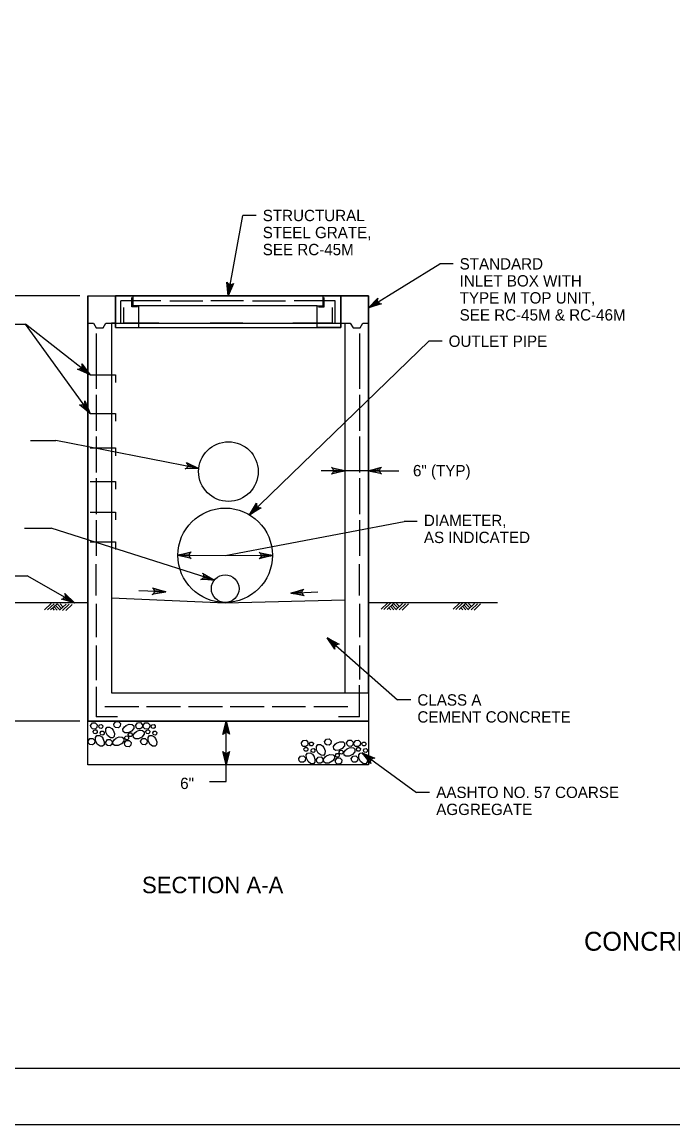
# Model space of a CAD drawing. Extents: x 636462 to 639890, y 299944 to 300538.
# Drawn here: x 639148.1 to 639320.2, y 299944.4 to 300236.1 of the extents above; entities that cross this region are included whole.
import ezdxf

# ---------------------------------------------------------------- set-up
doc = ezdxf.new("R2010")
doc.units = 0
for name, color, linetype in [('1', 7, 'Continuous'), ('Default', 7, 'Continuous'), ('PLT-BNDY', 7, 'Continuous')]:
    doc.layers.add(name, color=color, linetype=linetype)

msp = doc.modelspace()

# ---------------------------------------------------------------- linework, layer by layer
at = {"layer": '1'}
msp.add_lwpolyline([(639810.91, 299959.45), (639810.91, 300523.45), (639024.91, 300523.45), (639024.91, 299959.45), (639810.91, 299959.45), (639810.91, 299985.81), (639610.91, 299985.81), (639610.91, 300050.49), (639810.91, 300050.49), (639810.91, 300079.45), (639610.91, 300079.45), (639610.91, 299959.45), (639689.72, 299959.45), (639689.72, 299985.81), (639689.72, 299959.45), (639766.72, 299959.45), (639766.72, 299985.81), (639766.72, 299973.49), (639810.91, 299973.49)], dxfattribs=at)
at = {"layer": 'Default'}
for p, q in [((639202.59, 300163.65), (639206.52, 300184.9)), ((639210.01, 300184.9), (639206.52, 300184.9)), ((639239.68, 300160.5), (639258.57, 300172.12)), ((639262.07, 300172.12), (639258.57, 300172.12)), ((639163.38, 300163.65), (639084.63, 300163.65)), ((639165.5, 300163.65), (639165.5, 300051.22)), ((639165.5, 300163.65), (639239.68, 300163.65)), ((639172.8, 300155.32), (639172.8, 300163.65)), ((639232.38, 300163.65), (639172.8, 300163.65)), ((639177.17, 300160.73), (639177.17, 300163.25)), ((639177.48, 300161.04), (639177.48, 300163.65)), ((639227.7, 300161.04), (639227.7, 300163.65)), ((639228.01, 300160.73), (639228.01, 300163.25)), ((639232.38, 300155.32), (639232.38, 300163.65)), ((639239.68, 300163.65), (639239.68, 300051.22)), ((639174.23, 300156.34), (639174.23, 300162.34)), ((639184.84, 300162.34), (639174.23, 300162.34)), ((639174.99, 300156.4), (639174.99, 300160.6)), ((639178.68, 300160.73), (639177.17, 300160.73)), ((639177.48, 300161.04), (639179.04, 300161.04)), ((639179.04, 300155.32), (639179.04, 300161.04)), ((639226.14, 300161.04), (639179.04, 300161.04)), ((639187.23, 300162.34), (639195.92, 300162.34)), ((639206.7, 300162.34), (639198.01, 300162.34)), ((639209.09, 300162.34), (639217.79, 300162.34)), ((639230.95, 300162.34), (639220.06, 300162.34)), ((639226.14, 300155.32), (639226.14, 300161.04)), ((639226.14, 300161.04), (639227.7, 300161.04)), ((639226.5, 300160.73), (639228.01, 300160.73)), ((639230.19, 300156.4), (639230.19, 300160.6)), ((639230.95, 300156.34), (639230.95, 300162.34)), ((639145.5, 300156.21), (639149, 300156.21)), ((639166.1, 300142.79), (639149, 300156.21)), ((639166.1, 300132.55), (639149, 300156.21)), ((639165.5, 300156.4), (639166.99, 300156.4)), ((639166.99, 300156.4), (639167.7, 300155.17)), ((639167.7, 300155.17), (639169.55, 300155.17)), ((639169.55, 300155.17), (639170.27, 300156.4)), ((639170.27, 300156.4), (639171.75, 300156.4)), ((639171.75, 300156.4), (639233.43, 300156.4)), ((639171.75, 300156.4), (639171.75, 300058.74)), ((639172.8, 300155.32), (639232.38, 300155.32)), ((639184.29, 300156.4), (639174.99, 300156.4)), ((639186.68, 300156.4), (639195.77, 300156.4)), ((639206.52, 300156.4), (639197.88, 300156.4)), ((639209.09, 300156.4), (639217.73, 300156.4)), ((639230.19, 300156.4), (639219.75, 300156.4)), ((639233.43, 300156.4), (639234.91, 300156.4)), ((639233.43, 300156.4), (639233.43, 300058.74)), ((639234.91, 300156.4), (639235.63, 300155.17)), ((639235.63, 300155.17), (639237.48, 300155.17)), ((639237.48, 300155.17), (639238.19, 300156.4)), ((639238.19, 300156.4), (639239.68, 300156.4)), ((639167.72, 300153.71), (639167.72, 300139.04)), ((639208.24, 300105.78), (639255.66, 300151.67)), ((639237.36, 300153.71), (639237.36, 300139.04)), ((639259.16, 300151.67), (639255.66, 300151.67)), ((639167.72, 300137.5), (639167.72, 300128)), ((639237.36, 300137.5), (639237.36, 300128)), ((639150.33, 300125.41), (639157.02, 300125.41)), ((639194.86, 300118.04), (639157.02, 300125.41)), ((639167.72, 300126.46), (639167.72, 300116.96)), ((639237.36, 300126.46), (639237.36, 300116.96)), ((639239.68, 300117.44), (639227.18, 300117.44)), ((639239.68, 300117.44), (639247.72, 300117.44)), ((639167.72, 300115.42), (639167.72, 300105.92)), ((639237.36, 300115.42), (639237.36, 300105.92)), ((639148.75, 300102.28), (639155.8, 300102.28)), ((639198.98, 300088.51), (639155.8, 300102.28)), ((639167.72, 300104.38), (639167.72, 300094.88)), ((639201.83, 300095.03), (639249.12, 300103.97)), ((639237.36, 300104.38), (639237.36, 300094.88)), ((639252.62, 300103.97), (639249.12, 300103.97)), ((639189.34, 300095.06), (639214.33, 300094.99)), ((639167.72, 300084.46), (639167.72, 300092.72)), ((639237.36, 300084.46), (639237.36, 300092.72)), ((639126.35, 300089.67), (639149.47, 300089.67)), ((639161.98, 300082.47), (639149.47, 300089.67)), ((639186.1, 300085.38), (639178.97, 300085.7)), ((639219.21, 300085.06), (639226.34, 300085.39)), ((639165.5, 300082.47), (639131.4, 300082.47)), ((639154.08, 300080.67), (639155.81, 300082.28)), ((639154.86, 300080.64), (639156.6, 300082.26)), ((639155.67, 300080.61), (639157.41, 300082.23)), ((639156.58, 300081.46), (639157.44, 300080.55)), ((639156.96, 300081.81), (639158.08, 300080.61)), ((639157.38, 300082.24), (639158.52, 300081.01)), ((639158, 300080.53), (639159.75, 300082.16)), ((639158.19, 300082.21), (639158.93, 300081.41)), ((639158.85, 300080.5), (639160.58, 300082.1)), ((639159.66, 300080.47), (639161.38, 300082.08)), ((639167.72, 300082.25), (639167.72, 300073.44)), ((639171.75, 300083.84), (639201.83, 300082.47)), ((639201.83, 300082.47), (639233.43, 300083.31)), ((639237.36, 300082.25), (639237.36, 300073.44)), ((639239.68, 300082.57), (639273.79, 300082.57)), ((639243.03, 300080.79), (639244.76, 300082.41)), ((639243.81, 300080.77), (639245.55, 300082.39)), ((639244.62, 300080.74), (639246.36, 300082.36)), ((639245.11, 300081.2), (639245.6, 300080.68)), ((639245.53, 300081.59), (639246.38, 300080.68)), ((639245.9, 300081.94), (639247.02, 300080.74)), ((639246.32, 300082.36), (639247.47, 300081.14)), ((639246.95, 300080.66), (639248.7, 300082.29)), ((639247.13, 300082.33), (639247.88, 300081.53)), ((639247.8, 300080.63), (639249.52, 300082.23)), ((639248.61, 300080.6), (639250.33, 300082.2)), ((639262.07, 300080.79), (639263.8, 300082.41)), ((639262.85, 300080.77), (639264.59, 300082.39)), ((639263.66, 300080.74), (639265.4, 300082.36)), ((639264.15, 300081.2), (639264.64, 300080.68)), ((639264.57, 300081.59), (639265.42, 300080.68)), ((639264.94, 300081.94), (639266.06, 300080.74)), ((639265.36, 300082.36), (639266.51, 300081.14)), ((639265.99, 300080.66), (639267.74, 300082.29)), ((639266.17, 300082.33), (639266.92, 300081.53)), ((639266.84, 300080.63), (639268.56, 300082.23)), ((639267.65, 300080.6), (639269.37, 300082.2)), ((639156.17, 300081.07), (639156.65, 300080.55)), ((639228.79, 300073.25), (639247.41, 300056.82)), ((639167.72, 300071.18), (639167.72, 300062.09)), ((639237.36, 300071.18), (639237.36, 300062.19)), ((639167.72, 300060.25), (639167.72, 300052.38)), ((639171.75, 300058.74), (639233.43, 300058.74)), ((639237.36, 300052.38), (639237.36, 300060.76)), ((639169.98, 300055.12), (639178.97, 300055.12)), ((639181.04, 300055.12), (639190.04, 300055.12)), ((639192.11, 300055.12), (639201.1, 300055.12)), ((639203.17, 300055.12), (639212.17, 300055.12)), ((639214.24, 300055.12), (639223.05, 300055.12)), ((639225.3, 300055.12), (639234.29, 300055.12)), ((639250.9, 300056.82), (639247.41, 300056.82)), ((639173.33, 300052.38), (639167.72, 300052.38)), ((639237.36, 300052.38), (639231.75, 300052.38)), ((639163.38, 300051.22), (639084.63, 300051.22)), ((639239.68, 300051.22), (639165.5, 300051.22)), ((639238.03, 300042.81), (639252.38, 300032.39)), ((639255.88, 300032.39), (639252.38, 300032.39))]:
    msp.add_line(p, q, dxfattribs=at)
for points in [[(639203.76, 300166.72), (639204.03, 300166.95), (639202.59, 300163.65), (639203.76, 300166.72), (639203.36, 300166.59), (639202.59, 300163.65), (639202.84, 300166.68), (639202.51, 300166.92), (639202.59, 300163.65), (639202.3, 300167.24), (639202.51, 300166.92)], [(639242.77, 300161.62), (639243.12, 300161.57), (639239.68, 300160.5), (639242.77, 300161.62), (639242.41, 300161.84), (639239.68, 300160.5), (639242.14, 300162.29), (639242.1, 300162.7), (639239.68, 300160.5), (639242.21, 300163.06), (639242.1, 300162.7)], [(639163.98, 300145.31), (639163.91, 300145.65), (639166.1, 300142.79), (639163.98, 300145.31), (639163.9, 300144.89), (639166.1, 300142.79), (639163.58, 300144.48), (639163.2, 300144.3), (639166.1, 300142.79), (639162.82, 300144.28), (639163.2, 300144.3)], [(639166.1, 300142.79), (639172.8, 300142.79), (639172.8, 300140.74)], [(639164.71, 300135.54), (639164.73, 300135.89), (639166.1, 300132.55), (639164.71, 300135.54), (639164.52, 300135.16), (639166.1, 300132.55), (639164.1, 300134.84), (639163.69, 300134.77), (639166.1, 300132.55), (639163.32, 300134.85), (639163.69, 300134.77)], [(639166.1, 300132.55), (639172.8, 300132.55), (639172.8, 300130.51)], [(639166.1, 300123.44), (639172.8, 300123.44), (639172.8, 300121.4)], [(639191.82, 300119.33), (639191.6, 300119.6), (639194.86, 300118.04), (639191.82, 300119.33), (639191.94, 300118.92), (639194.86, 300118.04), (639191.84, 300118.41), (639191.58, 300118.08), (639194.86, 300118.04), (639191.26, 300117.89), (639191.58, 300118.08)], [(639230.19, 300118.06), (639229.93, 300118.29), (639233.43, 300117.44), (639230.19, 300118.06), (639230.39, 300117.69), (639233.43, 300117.44), (639230.4, 300117.17), (639230.22, 300116.79), (639233.43, 300117.44), (639229.94, 300116.54), (639230.22, 300116.79)], [(639242.91, 300116.82), (639243.18, 300116.6), (639239.68, 300117.44), (639242.91, 300116.82), (639242.71, 300117.19), (639239.68, 300117.44), (639242.7, 300117.72), (639242.88, 300118.09), (639239.68, 300117.44), (639243.16, 300118.35), (639242.88, 300118.09)], [(639166.1, 300114.56), (639172.8, 300114.56), (639172.8, 300112.51)], [(639211.02, 300107.56), (639211.37, 300107.59), (639208.24, 300105.78), (639211.02, 300107.56), (639210.62, 300107.7), (639208.24, 300105.78), (639210.25, 300108.07), (639210.12, 300108.47), (639208.24, 300105.78), (639210.15, 300108.84), (639210.12, 300108.47)], [(639166.1, 300106.5), (639172.8, 300106.5), (639172.8, 300104.45)], [(639166.1, 300098.64), (639172.8, 300098.64), (639172.8, 300096.59)], [(639192.57, 300094.42), (639192.84, 300094.19), (639189.34, 300095.06), (639192.57, 300094.42), (639192.38, 300094.79), (639189.34, 300095.06), (639192.37, 300095.31), (639192.56, 300095.69), (639189.34, 300095.06), (639192.84, 300095.94), (639192.56, 300095.69)], [(639211.09, 300095.62), (639210.82, 300095.84), (639214.33, 300094.99), (639211.09, 300095.62), (639211.29, 300095.25), (639214.33, 300094.99), (639211.3, 300094.72), (639211.12, 300094.35), (639214.33, 300094.99), (639210.84, 300094.09), (639211.12, 300094.35)], [(639196.06, 300090.04), (639195.86, 300090.33), (639198.98, 300088.51), (639196.06, 300090.04), (639196.14, 300089.62), (639198.98, 300088.51), (639196, 300089.12), (639195.72, 300088.81), (639198.98, 300088.51), (639195.38, 300088.65), (639195.72, 300088.81)], [(639159.52, 300084.66), (639159.4, 300084.99), (639161.98, 300082.47), (639159.52, 300084.66), (639159.5, 300084.24), (639161.98, 300082.47), (639159.24, 300083.79), (639158.89, 300083.56), (639161.98, 300082.47), (639158.52, 300083.48), (639158.89, 300083.56)], [(639182.9, 300086.19), (639182.64, 300086.42), (639186.1, 300085.38), (639182.9, 300086.19), (639183.08, 300085.8), (639186.1, 300085.38), (639183.06, 300085.28), (639182.85, 300084.91), (639186.1, 300085.38), (639182.56, 300084.68), (639182.85, 300084.91)], [(639222.47, 300084.59), (639222.75, 300084.38), (639219.21, 300085.06), (639222.47, 300084.59), (639222.26, 300084.95), (639219.21, 300085.06), (639222.22, 300085.48), (639222.39, 300085.86), (639219.21, 300085.06), (639222.66, 300086.13), (639222.39, 300085.86)], [(639230.77, 300070.62), (639230.82, 300070.27), (639228.79, 300073.25), (639230.77, 300070.62), (639230.87, 300071.03), (639228.79, 300073.25), (639231.22, 300071.42), (639231.6, 300071.58), (639228.79, 300073.25), (639231.98, 300071.58), (639231.6, 300071.58)], [(639166.26, 300050.09), (639166.73, 300050.75), (639167.49, 300050.8), (639168.01, 300050.26), (639167.93, 300049.5), (639167.47, 300049.11), (639166.73, 300049.17), (639166.38, 300049.5), (639166.26, 300050.09)], [(639168.4, 300049.88), (639168.69, 300050.28), (639169.14, 300050.31), (639169.45, 300049.98), (639169.4, 300049.53), (639169.12, 300049.3), (639168.68, 300049.33), (639168.47, 300049.53), (639168.4, 300049.88)], [(639172.22, 300048.86), (639172.56, 300047.99), (639172.49, 300047.18), (639172.13, 300046.79), (639171.47, 300046.81), (639170.73, 300047.39), (639170.28, 300048.29), (639170.26, 300049.14), (639170.6, 300049.61), (639171.28, 300049.66), (639171.88, 300049.27), (639172.24, 300048.83)], [(639172.41, 300050.45), (639172.88, 300051.11), (639173.63, 300051.16), (639174.15, 300050.62), (639174.07, 300049.86), (639173.61, 300049.47), (639172.87, 300049.53), (639172.52, 300049.86), (639172.41, 300050.44)], [(639175.59, 300050.05), (639176.47, 300050.4), (639177.28, 300050.33), (639177.66, 300049.97), (639177.65, 300049.31), (639177.06, 300048.57), (639176.16, 300048.12), (639175.32, 300048.1), (639174.84, 300048.44), (639174.79, 300049.12), (639175.18, 300049.72), (639175.62, 300050.08)], [(639178.21, 300050.11), (639178.68, 300050.78), (639179.43, 300050.83), (639179.95, 300050.28), (639179.88, 300049.53), (639179.41, 300049.14), (639178.67, 300049.19), (639178.32, 300049.53), (639178.21, 300050.11)], [(639180.14, 300050.09), (639180.61, 300050.75), (639181.36, 300050.8), (639181.89, 300050.26), (639181.81, 300049.5), (639181.35, 300049.11), (639180.61, 300049.17), (639180.26, 300049.5), (639180.14, 300050.09)], [(639182.28, 300049.88), (639182.56, 300050.28), (639183.01, 300050.31), (639183.33, 300049.98), (639183.28, 300049.53), (639183, 300049.3), (639182.56, 300049.33), (639182.35, 300049.53), (639182.28, 300049.88)], [(639197.65, 300035.28), (639202.07, 300035.28), (639202.07, 300051.22)], [(639201.47, 300047.98), (639201.25, 300047.71), (639202.07, 300051.22), (639201.47, 300047.98), (639201.84, 300048.18), (639202.07, 300051.22), (639202.37, 300048.19), (639202.74, 300048.01), (639202.07, 300051.22), (639203, 300047.74), (639202.74, 300048.01)], [(639165.59, 300045.93), (639166.06, 300046.6), (639166.81, 300046.64), (639167.33, 300046.1), (639167.26, 300045.34), (639166.79, 300044.96), (639166.05, 300045.01), (639165.7, 300045.35), (639165.59, 300045.93)], [(639166.95, 300048.47), (639167.23, 300048.87), (639167.68, 300048.9), (639167.99, 300048.57), (639167.95, 300048.12), (639167.67, 300047.88), (639167.23, 300047.92), (639167.02, 300048.12), (639166.95, 300048.47)], [(639169.51, 300046.65), (639169.86, 300045.77), (639169.79, 300044.96), (639169.42, 300044.58), (639168.77, 300044.59), (639168.02, 300045.17), (639167.57, 300046.07), (639167.56, 300046.92), (639167.9, 300047.4), (639168.57, 300047.44), (639169.18, 300047.06), (639169.53, 300046.61)], [(639168.8, 300048.14), (639169.08, 300048.54), (639169.53, 300048.56), (639169.85, 300048.24), (639169.8, 300047.79), (639169.52, 300047.55), (639169.08, 300047.59), (639168.87, 300047.79), (639168.8, 300048.14)], [(639170.23, 300045.66), (639170.7, 300046.33), (639171.45, 300046.37), (639171.98, 300045.83), (639171.9, 300045.07), (639171.44, 300044.69), (639170.7, 300044.74), (639170.35, 300045.08), (639170.23, 300045.66)], [(639172.94, 300046.69), (639173.82, 300047.04), (639174.63, 300046.97), (639175.01, 300046.6), (639175, 300045.95), (639174.42, 300045.2), (639173.52, 300044.75), (639172.67, 300044.74), (639172.19, 300045.08), (639172.15, 300045.75), (639172.54, 300046.36), (639172.98, 300046.71)], [(639175.25, 300046.88), (639175.53, 300047.28), (639175.98, 300047.31), (639176.3, 300046.98), (639176.25, 300046.53), (639175.97, 300046.3), (639175.53, 300046.33), (639175.32, 300046.53), (639175.25, 300046.88)], [(639176.22, 300047.7), (639176.5, 300048.1), (639176.95, 300048.12), (639177.27, 300047.8), (639177.22, 300047.34), (639176.94, 300047.11), (639176.5, 300047.15), (639176.29, 300047.35), (639176.22, 300047.7)], [(639178.32, 300048.48), (639179.2, 300048.83), (639180, 300048.76), (639180.39, 300048.4), (639180.37, 300047.74), (639179.79, 300047), (639178.89, 300046.55), (639178.04, 300046.53), (639177.57, 300046.87), (639177.52, 300047.55), (639177.91, 300048.15), (639178.35, 300048.5)], [(639179.47, 300045.93), (639179.94, 300046.6), (639180.69, 300046.64), (639181.21, 300046.1), (639181.13, 300045.34), (639180.67, 300044.96), (639179.93, 300045.01), (639179.58, 300045.35), (639179.47, 300045.93)], [(639180.83, 300048.47), (639181.11, 300048.87), (639181.56, 300048.9), (639181.87, 300048.57), (639181.83, 300048.12), (639181.55, 300047.88), (639181.1, 300047.92), (639180.9, 300048.12), (639180.83, 300048.47)], [(639183.39, 300046.65), (639183.74, 300045.77), (639183.67, 300044.96), (639183.3, 300044.58), (639182.65, 300044.59), (639181.9, 300045.17), (639181.45, 300046.07), (639181.44, 300046.92), (639181.78, 300047.4), (639182.45, 300047.44), (639183.06, 300047.06), (639183.41, 300046.61)], [(639182.68, 300048.14), (639182.96, 300048.54), (639183.41, 300048.56), (639183.72, 300048.24), (639183.68, 300047.79), (639183.4, 300047.55), (639182.96, 300047.59), (639182.75, 300047.79), (639182.68, 300048.14)], [(639228.12, 300045.83), (639228.59, 300046.49), (639229.34, 300046.54), (639229.86, 300046), (639229.79, 300045.24), (639229.32, 300044.85), (639228.58, 300044.91), (639228.23, 300045.24), (639228.12, 300045.83)], [(639233.93, 300045.49), (639234.4, 300046.16), (639235.15, 300046.21), (639235.67, 300045.66), (639235.59, 300044.91), (639235.13, 300044.52), (639234.39, 300044.58), (639234.04, 300044.91), (639233.93, 300045.49)], [(639175.22, 300045.41), (639175.69, 300046.08), (639176.44, 300046.12), (639176.96, 300045.58), (639176.89, 300044.82), (639176.42, 300044.44), (639175.68, 300044.49), (639175.33, 300044.83), (639175.22, 300045.41)], [(639221.98, 300045.47), (639222.45, 300046.13), (639223.2, 300046.18), (639223.72, 300045.64), (639223.65, 300044.88), (639223.18, 300044.49), (639222.44, 300044.55), (639222.09, 300044.89), (639221.98, 300045.47)], [(639222.66, 300043.85), (639222.95, 300044.25), (639223.4, 300044.28), (639223.71, 300043.95), (639223.66, 300043.5), (639223.39, 300043.27), (639222.94, 300043.3), (639222.73, 300043.5), (639222.66, 300043.85)], [(639224.12, 300045.26), (639224.4, 300045.66), (639224.85, 300045.69), (639225.16, 300045.36), (639225.12, 300044.91), (639224.84, 300044.68), (639224.4, 300044.71), (639224.19, 300044.91), (639224.12, 300045.26)], [(639224.51, 300043.52), (639224.8, 300043.92), (639225.25, 300043.94), (639225.56, 300043.62), (639225.51, 300043.17), (639225.24, 300042.93), (639224.79, 300042.97), (639224.58, 300043.17), (639224.52, 300043.52)], [(639227.93, 300044.24), (639228.28, 300043.37), (639228.21, 300042.56), (639227.84, 300042.17), (639227.19, 300042.19), (639226.44, 300042.77), (639225.99, 300043.67), (639225.98, 300044.52), (639226.32, 300045), (639226.99, 300045.04), (639227.6, 300044.65), (639227.95, 300044.21)], [(639231.3, 300045.43), (639232.18, 300045.78), (639232.99, 300045.71), (639233.37, 300045.35), (639233.36, 300044.69), (639232.78, 300043.95), (639231.88, 300043.5), (639231.03, 300043.48), (639230.55, 300043.82), (639230.51, 300044.5), (639230.9, 300045.1), (639231.34, 300045.46)], [(639231.94, 300043.08), (639232.22, 300043.48), (639232.67, 300043.5), (639232.98, 300043.18), (639232.94, 300042.73), (639232.66, 300042.49), (639232.21, 300042.53), (639232.01, 300042.73), (639231.94, 300043.08)], [(639234.03, 300043.86), (639234.91, 300044.21), (639235.72, 300044.14), (639236.1, 300043.78), (639236.09, 300043.12), (639235.51, 300042.38), (639234.61, 300041.93), (639233.76, 300041.91), (639233.28, 300042.25), (639233.24, 300042.93), (639233.62, 300043.53), (639234.07, 300043.88)], [(639235.86, 300045.47), (639236.33, 300046.13), (639237.08, 300046.18), (639237.6, 300045.64), (639237.53, 300044.88), (639237.06, 300044.49), (639236.32, 300044.55), (639235.97, 300044.89), (639235.86, 300045.47)], [(639236.54, 300043.85), (639236.82, 300044.25), (639237.27, 300044.28), (639237.59, 300043.95), (639237.54, 300043.5), (639237.26, 300043.27), (639236.82, 300043.3), (639236.61, 300043.5), (639236.54, 300043.85)], [(639238, 300045.26), (639238.28, 300045.66), (639238.73, 300045.69), (639239.04, 300045.36), (639239, 300044.91), (639238.72, 300044.68), (639238.27, 300044.71), (639238.07, 300044.91), (639238, 300045.26)], [(639238.39, 300043.52), (639238.68, 300043.92), (639239.13, 300043.94), (639239.44, 300043.62), (639239.39, 300043.17), (639239.12, 300042.93), (639238.67, 300042.97), (639238.46, 300043.17), (639238.39, 300043.52)], [(639202.73, 300042.92), (639202.95, 300043.19), (639202.07, 300039.69), (639202.73, 300042.92), (639202.35, 300042.73), (639202.07, 300039.69), (639201.83, 300042.72), (639201.45, 300042.91), (639202.07, 300039.69), (639201.2, 300043.19), (639201.45, 300042.91)], [(639221.3, 300041.31), (639221.77, 300041.98), (639222.52, 300042.02), (639223.05, 300041.48), (639222.97, 300040.72), (639222.51, 300040.34), (639221.77, 300040.39), (639221.42, 300040.73), (639221.31, 300041.31)], [(639225.23, 300042.03), (639225.57, 300041.15), (639225.5, 300040.34), (639225.14, 300039.96), (639224.48, 300039.97), (639223.74, 300040.55), (639223.29, 300041.45), (639223.27, 300042.3), (639223.61, 300042.78), (639224.29, 300042.82), (639224.89, 300042.44), (639225.25, 300041.99)], [(639225.95, 300041.04), (639226.42, 300041.71), (639227.17, 300041.75), (639227.69, 300041.21), (639227.62, 300040.45), (639227.15, 300040.07), (639226.41, 300040.12), (639226.06, 300040.46), (639225.95, 300041.04)], [(639228.66, 300042.07), (639229.54, 300042.42), (639230.35, 300042.35), (639230.73, 300041.99), (639230.72, 300041.33), (639230.14, 300040.59), (639229.23, 300040.14), (639228.39, 300040.12), (639227.91, 300040.46), (639227.86, 300041.14), (639228.25, 300041.74), (639228.69, 300042.09)], [(639230.94, 300040.79), (639231.41, 300041.46), (639232.16, 300041.5), (639232.68, 300040.96), (639232.6, 300040.21), (639232.14, 300039.82), (639231.4, 300039.87), (639231.05, 300040.21), (639230.94, 300040.79)], [(639230.97, 300042.26), (639231.25, 300042.66), (639231.7, 300042.69), (639232.01, 300042.36), (639231.97, 300041.91), (639231.69, 300041.68), (639231.24, 300041.71), (639231.03, 300041.91), (639230.97, 300042.26)], [(639235.18, 300041.31), (639235.65, 300041.98), (639236.4, 300042.02), (639236.92, 300041.48), (639236.85, 300040.72), (639236.39, 300040.34), (639235.64, 300040.39), (639235.3, 300040.73), (639235.18, 300041.31)], [(639239.1, 300042.03), (639239.45, 300041.15), (639239.38, 300040.34), (639239.02, 300039.96), (639238.36, 300039.97), (639237.62, 300040.55), (639237.17, 300041.45), (639237.15, 300042.3), (639237.49, 300042.78), (639238.17, 300042.82), (639238.77, 300042.44), (639239.13, 300041.99)], [(639240.25, 300040.37), (639240.33, 300040.03), (639238.03, 300042.81), (639240.25, 300040.37), (639240.31, 300040.78), (639238.03, 300042.81), (639240.62, 300041.21), (639240.99, 300041.4), (639238.03, 300042.81), (639241.37, 300041.43), (639240.99, 300041.4)]]:
    msp.add_lwpolyline(points, dxfattribs=at)
for points in [[(639239.68, 300058.67), (639239.68, 300051.22), (639165.5, 300051.22), (639165.5, 300156.4), (639165.5, 300163.65), (639172.8, 300163.65), (639172.8, 300156.4), (639171.75, 300156.4), (639171.75, 300083.84), (639201.83, 300082.47), (639233.43, 300083.31), (639233.43, 300058.67)], [(639177.48, 300163.65), (639172.8, 300163.65), (639172.8, 300155.32), (639179.04, 300155.32), (639179.04, 300161.04), (639177.48, 300161.04)], [(639226.14, 300161.04), (639227.7, 300161.04), (639227.7, 300163.65), (639232.38, 300163.65), (639232.38, 300155.32), (639226.14, 300155.32)], [(639239.68, 300156.4), (639239.68, 300163.65), (639232.38, 300163.65), (639232.38, 300156.4), (639233.43, 300156.4), (639233.43, 300058.67), (639239.68, 300058.67)], [(639165.5, 300051.22), (639239.72, 300051.22), (639239.72, 300039.69), (639165.5, 300039.69)]]:
    msp.add_lwpolyline(points, close=True, dxfattribs=at)
for centre, radius in [((639202.69, 300117.19), 7.88), ((639201.83, 300095.06), 12.49), ((639201.83, 300086.23), 3.66)]:
    msp.add_circle(centre, radius, dxfattribs=at)
at = {"layer": 'PLT-BNDY'}
msp.add_lwpolyline([(638984.91, 300538.45), (639825.91, 300538.45), (639825.91, 299944.45), (638984.91, 299944.45)], close=True, dxfattribs=at)

# ---------------------------------------------------------------- texts
at = {"layer": 'Default'}
for s, height, p in [('STRUCTURAL', 2.998, (639211.76, 300183.41)), ('STEEL GRATE, ', 2.998, (639211.76, 300178.91)), ('SEE RC-45M', 2.998, (639211.76, 300174.41)), ('STANDARD', 2.998, (639263.82, 300170.62)), ('INLET BOX WITH', 2.998, (639263.82, 300166.13)), ('TYPE M TOP UNIT,', 2.998, (639263.82, 300161.63)), ('SEE RC-45M & RC-46M', 2.998, (639263.82, 300157.13)), ('OUTLET PIPE', 2.998, (639260.91, 300150.17)), ('6" (TYP)', 2.998, (639251.48, 300115.95)), ('DIAMETER,', 2.998, (639254.37, 300102.8)), ('AS INDICATED', 2.998, (639254.37, 300098.3)), ('CLASS A', 2.998, (639252.65, 300055.32)), ('CEMENT CONCRETE', 2.998, (639252.65, 300050.83)), ('6"', 2.998, (639189.93, 300033.26)), ('AASHTO NO. 57 COARSE', 2.998, (639257.63, 300030.89)), ('AGGREGATE', 2.998, (639257.63, 300026.39)), ('SECTION A-A', 4.3721, (639179.84, 300005.71)), ('CONCRETE OUTLET STRUCTURE', 4.9967, (639296.71, 299990.51))]:
    msp.add_text(s, height=height, dxfattribs=at).set_placement(p)

doc.saveas('drawing.dxf')
